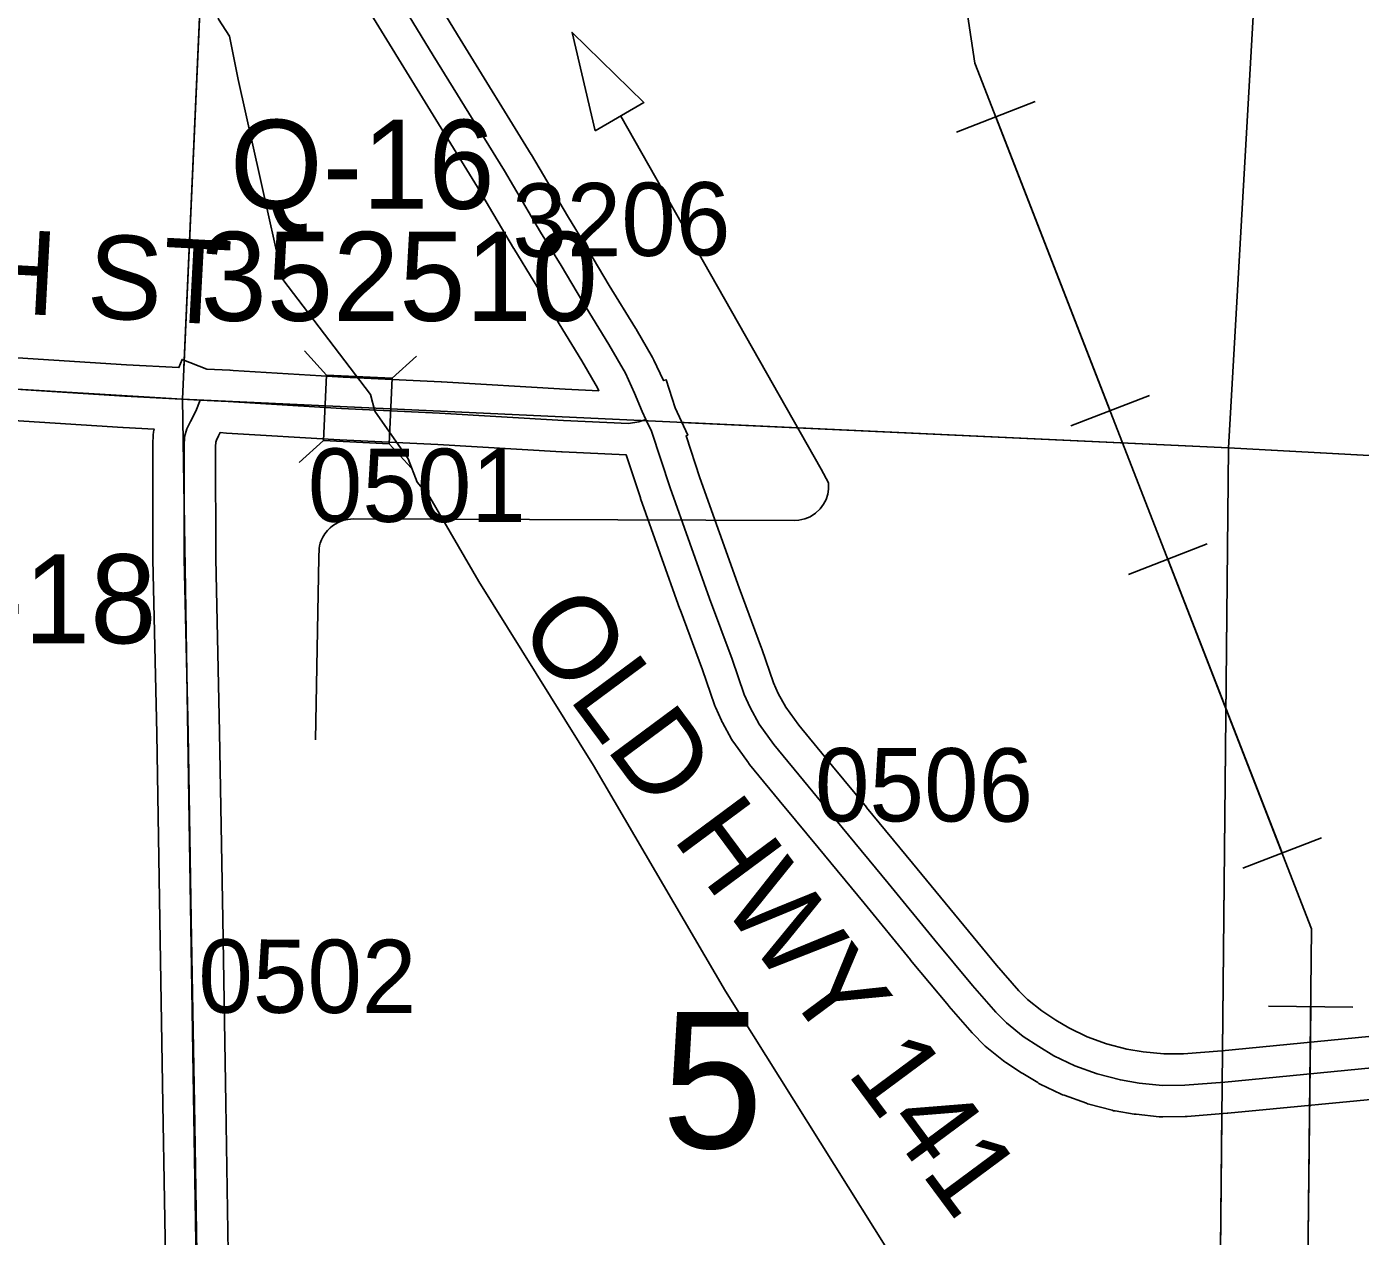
# Model space of a CAD drawing. Extents: x -157.2 to -99.3, y 12.2 to 46.2.
# Drawn here: x -139.945 to -138.672, y 28.173 to 29.328 of the extents above; entities that cross this region are included whole.
import ezdxf

# ---------------------------------------------------------------- set-up
doc = ezdxf.new("R2010")
doc.units = 0
for name, color, linetype in [('tdCoDirctArrow', 7, 'Continuous'), ('tdCoHydroRiver', 7, 'Continuous'), ('tdCoPipe', 7, 'Continuous'), ('tdCoSecRdNmbr', 7, 'Continuous'), ('tdCoSecRdTxt', 7, 'Continuous'), ('tdCoSecRteBand', 7, 'Continuous'), ('tdCoSecRteCL', 7, 'Continuous'), ('tdCoSectLine', 7, 'Continuous'), ('tdCoSectLinePart', 7, 'Continuous'), ('tdCoSectNmbr', 7, 'Continuous'), ('tdCoStrucSec', 7, 'Continuous'), ('tdCoStrucSecCoName', 7, 'Continuous'), ('tdCoStrucSecFHWANum', 7, 'Continuous'), ('tdCoSurfAsphalt', 7, 'Continuous'), ('tdCoSurfGravel', 7, 'Continuous'), ('tdCoTwpBndry', 7, 'Continuous'), ('tdCoTwpBndryShd', 7, 'Continuous')]:
    doc.layers.add(name, color=color, linetype=linetype)

msp = doc.modelspace()

# ---------------------------------------------------------------- linework, layer by layer
at = {"layer": 'tdCoDirctArrow'}
msp.add_lwpolyline([(-139.4023, 29.2282), (-139.4242, 29.3221), (-139.3557, 29.2552)], close=True, dxfattribs=at)
msp.add_lwpolyline([(-139.6693, 28.6465), (-139.666, 28.8206), (-139.6658, 28.8292), (-139.6653, 28.8319), (-139.6648, 28.8344), (-139.6636, 28.8375), (-139.6622, 28.8403), (-139.6602, 28.8434), (-139.6578, 28.8464), (-139.6553, 28.849), (-139.6531, 28.8509), (-139.6504, 28.8527), (-139.6476, 28.8542), (-139.6448, 28.8555), (-139.6422, 28.8563), (-139.6382, 28.8571), (-139.6332, 28.8576), (-139.2124, 28.856), (-139.2079, 28.8565), (-139.2021, 28.8576), (-139.1971, 28.8596), (-139.192, 28.8632), (-139.1875, 28.8672), (-139.1843, 28.8715), (-139.1818, 28.8761), (-139.1802, 28.8811), (-139.1795, 28.8861), (-139.1796, 28.8921), (-139.1864, 28.9051), (-139.3778, 29.242)], dxfattribs=at)
at = {"layer": 'tdCoHydroRiver'}
msp.add_lwpolyline([(-139.834, 29.7033), (-139.8556, 29.6693), (-139.879, 29.5784), (-139.8658, 29.5448), (-139.7953, 29.4273), (-139.7659, 29.3569), (-139.7619, 29.3347), (-139.7513, 29.3185), (-139.7431, 29.2772), (-139.7002, 29.0863), (-139.6168, 28.9763), (-139.6125, 28.9604), (-139.5808, 28.9151), (-139.572, 28.8928), (-139.5599, 28.8782), (-139.5134, 28.7977), (-139.4037, 28.6221), (-139.2778, 28.4065), (-139.0702, 28.0755)], dxfattribs=at)
at = {"layer": 'tdCoPipe'}
for p, q in [((-138.9822, 29.256), (-139.0573, 29.2268)), ((-138.8731, 28.9755), (-138.9481, 28.9463)), ((-138.818, 28.8338), (-138.8931, 28.8046)), ((-138.7089, 28.5532), (-138.7839, 28.524)), ((-138.6789, 28.3914), (-138.7595, 28.3923))]:
    msp.add_line(p, q, dxfattribs=at)
for points in [[(-136.934, 22.5495), (-137.7242, 24.8933), (-138.4968, 27.1666), (-138.4114, 27.2635), (-138.4614, 27.8735), (-138.7227, 28.0895), (-138.7183, 28.4663), (-139.0397, 29.2926), (-139.1184, 29.8198), (-140.0614, 32.629), (-140.3902, 33.7747), (-140.3873, 34.3489), (-140.6033, 34.3601), (-141.0238, 35.5765), (-141.1818, 36.0085), (-141.3937, 37.236), (-141.4233, 37.6118), (-141.6227, 37.7022), (-142.0941, 39.016), (-142.2605, 40.1621), (-142.7574, 40.5833), (-142.8772, 41.3829)], [(-138.9106, 28.9609), (-139.0197, 29.2414)], [(-138.7464, 28.5386), (-138.8555, 28.8192)], [(-138.7227, 28.0908), (-138.7192, 28.3918)]]:
    msp.add_lwpolyline(points, dxfattribs=at)
at = {"layer": 'tdCoSecRteBand'}
for points in [[(-139.5737, 29.3856), (-139.5311, 29.3158), (-139.4633, 29.2056), (-139.4632, 29.2054), (-139.463, 29.2052), (-139.4286, 29.1469), (-139.4092, 29.115), (-139.4091, 29.1149), (-139.4091, 29.1148), (-139.3887, 29.0806), (-139.3636, 29.0396), (-139.3634, 29.0393), (-139.3632, 29.0389), (-139.3475, 29.0116), (-139.3468, 29.0104), (-139.3463, 29.0093), (-139.3374, 28.9903), (-139.3371, 28.9898), (-139.3371, 28.9896), (-139.3346, 28.9904), (-139.3257, 28.9635), (-139.3139, 28.9377), (-139.3155, 28.937), (-139.3022, 28.8968), (-139.2648, 28.7918), (-139.2435, 28.734), (-139.2433, 28.7337), (-139.2432, 28.7334), (-139.2321, 28.7011), (-139.2275, 28.6909), (-139.2203, 28.6777), (-139.2079, 28.6605), (-139.1757, 28.6214), (-139.1432, 28.5822), (-139.1432, 28.5822), (-139.1431, 28.5821), (-139.0992, 28.5289), (-139.0992, 28.5288), (-139.0992, 28.5288), (-139.0549, 28.4746), (-139.0192, 28.4316), (-138.9978, 28.4071), (-138.9895, 28.3986), (-138.976, 28.3878), (-138.9626, 28.3791), (-138.95, 28.3715), (-138.9327, 28.3631), (-138.9142, 28.3564), (-138.8946, 28.3512), (-138.879, 28.3487), (-138.8594, 28.3467), (-138.8406, 28.3469), (-138.8039, 28.3498), (-138.6375, 28.3658)], [(-139.9537, 29.0114), (-139.8495, 29.0047), (-139.7995, 29.0021), (-139.7965, 29.0098), (-139.7729, 29.0007), (-139.7508, 28.9996), (-139.7507, 28.9996), (-139.7507, 28.9996), (-139.7477, 28.9994), (-139.7477, 28.9994), (-139.6427, 28.9929), (-139.5492, 28.9885), (-139.5491, 28.9885), (-139.5489, 28.9884), (-139.4308, 28.9814), (-139.3988, 28.98), (-139.4001, 28.9827), (-139.415, 29.0086), (-139.44, 29.0495), (-139.4401, 29.0496), (-139.4401, 29.0498), (-139.4605, 29.0839), (-139.48, 29.1159), (-139.4801, 29.1161), (-139.4802, 29.1162), (-139.5145, 29.1744), (-139.5822, 29.2844), (-139.5822, 29.2845), (-139.5823, 29.2845), (-139.6249, 29.3543)], [(-139.8118, 28.1154), (-139.8148, 28.2986), (-139.8177, 28.4746), (-139.8177, 28.4746), (-139.8177, 28.4746), (-139.8207, 28.6526), (-139.8244, 28.8187), (-139.8244, 28.819), (-139.8244, 28.8193), (-139.8246, 28.9274), (-139.8246, 28.9283), (-139.8246, 28.9292), (-139.8241, 28.9376), (-139.8239, 28.9408), (-139.8232, 28.9433), (-139.8528, 28.9448), (-139.853, 28.9448), (-139.8532, 28.9448), (-139.9574, 28.9515)], [(-138.6318, 28.3061), (-138.7984, 28.29), (-138.7987, 28.29), (-138.799, 28.29), (-138.837, 28.287), (-138.838, 28.2869), (-138.8389, 28.2869), (-138.8604, 28.2867), (-138.8621, 28.2867), (-138.8637, 28.2868), (-138.8859, 28.2891), (-138.8869, 28.2891), (-138.8878, 28.2893), (-138.9058, 28.2923), (-138.9073, 28.2925), (-138.9087, 28.2929), (-138.9309, 28.2988), (-138.9321, 28.2991), (-138.9333, 28.2996), (-138.9545, 28.3072), (-138.956, 28.3077), (-138.9574, 28.3084), (-138.9773, 28.318), (-138.9786, 28.3186), (-138.9798, 28.3194), (-138.9941, 28.328), (-138.9946, 28.3283), (-138.9951, 28.3286), (-139.0101, 28.3385), (-139.0113, 28.3392), (-139.0124, 28.3401), (-139.0284, 28.3529), (-139.0299, 28.3541), (-139.0312, 28.3554), (-139.0413, 28.3658), (-139.0419, 28.3664), (-139.0424, 28.367), (-139.0646, 28.3924), (-139.0648, 28.3927), (-139.0651, 28.393), (-139.1011, 28.4364), (-139.1012, 28.4364), (-139.1012, 28.4365), (-139.1456, 28.4907), (-139.1894, 28.5439), (-139.2219, 28.5831), (-139.222, 28.5832), (-139.222, 28.5832), (-139.2548, 28.6232), (-139.2554, 28.6239), (-139.256, 28.6247), (-139.27, 28.6441), (-139.2711, 28.6456), (-139.272, 28.6473), (-139.2807, 28.6631), (-139.2812, 28.6641), (-139.2817, 28.6651), (-139.2874, 28.6777), (-139.2879, 28.679), (-139.2884, 28.6802), (-139.2998, 28.7135), (-139.3212, 28.7711), (-139.3213, 28.7713), (-139.3213, 28.7715), (-139.3588, 28.877), (-139.3589, 28.8773), (-139.359, 28.8776), (-139.3727, 28.9188), (-139.4337, 28.9215), (-139.4339, 28.9215), (-139.4342, 28.9215), (-139.5523, 28.9285), (-139.6458, 28.933), (-139.646, 28.933), (-139.6462, 28.933), (-139.7541, 28.9396), (-139.7602, 28.94), (-139.7618, 28.9369), (-139.7638, 28.9328), (-139.7644, 28.9308), (-139.7646, 28.9266), (-139.7644, 28.8198), (-139.7607, 28.6539), (-139.7607, 28.6538), (-139.7607, 28.6537), (-139.7577, 28.4756), (-139.7548, 28.2996), (-139.7548, 28.2996), (-139.7548, 28.2996), (-139.7518, 28.1163)]]:
    msp.add_lwpolyline(points, dxfattribs=at)
at = {"layer": 'tdCoSecRteCL'}
for points in [[(-139.3537, 28.9524), (-139.3572, 28.9601), (-139.3646, 28.9776), (-139.3734, 28.9966), (-139.3892, 29.024), (-139.4144, 29.0651), (-139.4348, 29.0994), (-139.4543, 29.1315), (-139.4889, 29.1899), (-139.5567, 29.3002), (-139.5993, 29.3699)], [(-141.7835, 29.0328), (-141.7275, 29.0325), (-141.5837, 29.0322), (-141.4675, 29.0322), (-141.3625, 29.0335), (-141.1741, 29.0325), (-141.0592, 29.0325), (-140.9654, 29.0322), (-140.8404, 29.032), (-140.7795, 29.0315), (-140.7129, 29.0276), (-140.5687, 29.0169), (-140.5058, 29.0135), (-140.3884, 29.0046), (-140.3223, 28.997), (-140.2853, 28.995), (-140.2646, 28.9955), (-140.2155, 28.9962), (-140.1699, 28.994), (-140.1206, 28.9913), (-140.0133, 28.9846), (-139.9556, 28.9814), (-139.8513, 28.9748), (-139.7793, 28.971)], [(-139.7915, 26.9754), (-139.789, 27.1141), (-139.7867, 27.29), (-139.7853, 27.4549), (-139.7835, 27.633), (-139.7818, 27.8022), (-139.7798, 27.9708), (-139.7818, 28.1158), (-139.7848, 28.2991), (-139.7877, 28.4751), (-139.7907, 28.6532), (-139.7944, 28.8194), (-139.7946, 28.9274), (-139.7941, 28.9358), (-139.7919, 28.9437), (-139.7885, 28.9506), (-139.7833, 28.9605), (-139.7793, 28.971)], [(-139.7793, 28.971), (-139.7524, 28.9696), (-139.6444, 28.9629), (-139.5507, 28.9585), (-139.4324, 28.9514), (-139.3705, 28.9487), (-139.3604, 28.9502), (-139.3537, 28.9524)], [(-138.6346, 28.3359), (-138.8013, 28.3199), (-138.8393, 28.3169), (-138.8607, 28.3167), (-138.8829, 28.3189), (-138.9009, 28.3219), (-138.9231, 28.3278), (-138.9443, 28.3354), (-138.9643, 28.345), (-138.9786, 28.3537), (-138.9937, 28.3635), (-139.0097, 28.3764), (-139.0198, 28.3867), (-139.042, 28.4121), (-139.078, 28.4555), (-139.1224, 28.5098), (-139.1663, 28.563), (-139.1988, 28.6023), (-139.2316, 28.6422), (-139.2457, 28.6617), (-139.2543, 28.6775), (-139.26, 28.69), (-139.2716, 28.7236), (-139.293, 28.7815), (-139.3305, 28.8871), (-139.3485, 28.9413), (-139.3537, 28.9524)]]:
    msp.add_lwpolyline(points, dxfattribs=at)
at = {"layer": 'tdCoSectLine'}
for points in [[(-139.7961, 28.9719), (-139.7503, 29.9964)], [(-138.7976, 28.9254), (-138.7411, 29.9168)], [(-140.7866, 29.0316), (-139.7961, 28.9719)], [(-139.7961, 28.9719), (-138.7976, 28.9254)], [(-139.7803, 27.9656), (-139.7961, 28.9719)], [(-138.8076, 27.9332), (-138.7976, 28.9254)], [(-138.7976, 28.9254), (-137.7864, 28.8705)]]:
    msp.add_lwpolyline(points, dxfattribs=at)
at = {"layer": 'tdCoSectLinePart'}
for points in [[(-138.7976, 28.9254), (-138.7411, 29.9168)], [(-139.7948, 29.0017), (-139.769, 29.5789)], [(-139.3201, 28.9497), (-138.7976, 28.9254)], [(-138.8034, 28.3498), (-138.7976, 28.9254)], [(-138.7976, 28.9254), (-138.0562, 28.8851)], [(-138.8076, 27.9332), (-138.804, 28.2902)]]:
    msp.add_lwpolyline(points, dxfattribs=at)
at = {"layer": 'tdCoStrucSec'}
for p, q in [((-139.6586, 28.9949), (-139.6796, 29.0181)), ((-139.596, 28.992), (-139.5729, 29.013)), ((-139.6615, 28.9324), (-139.6847, 28.9113)), ((-139.599, 28.9294), (-139.5779, 28.9063))]:
    msp.add_line(p, q, dxfattribs=at)
msp.add_lwpolyline([(-139.6586, 28.9949), (-139.596, 28.992), (-139.599, 28.9294), (-139.6615, 28.9324)], close=True, dxfattribs=at)
at = {"layer": 'tdCoSurfAsphalt'}
for points in [[(-139.3537, 28.9524), (-139.3572, 28.9601), (-139.3646, 28.9776), (-139.3734, 28.9966), (-139.3892, 29.024), (-139.4144, 29.0651), (-139.4348, 29.0994), (-139.4543, 29.1315), (-139.4889, 29.1899), (-139.5567, 29.3002), (-139.5993, 29.3699), (-139.6228, 29.4082), (-139.6353, 29.4279), (-139.657, 29.4629), (-139.6778, 29.4966)], [(-138.6346, 28.3359), (-138.8013, 28.3199), (-138.8393, 28.3169), (-138.8607, 28.3167), (-138.8829, 28.3189), (-138.9009, 28.3219), (-138.9231, 28.3278), (-138.9443, 28.3354), (-138.9643, 28.345), (-138.9786, 28.3537), (-138.9937, 28.3635), (-139.0097, 28.3764), (-139.0198, 28.3867), (-139.042, 28.4121), (-139.078, 28.4555), (-139.1224, 28.5098), (-139.1663, 28.563), (-139.1988, 28.6023), (-139.2316, 28.6422), (-139.2457, 28.6617), (-139.2543, 28.6775), (-139.26, 28.69), (-139.2716, 28.7236), (-139.293, 28.7815), (-139.3305, 28.8871), (-139.3485, 28.9413), (-139.3537, 28.9524)]]:
    msp.add_lwpolyline(points, dxfattribs=at)
at = {"layer": 'tdCoSurfGravel'}
for points in [[(-139.9556, 28.9814), (-139.8513, 28.9748), (-139.7793, 28.971)], [(-139.803, 26.6128), (-139.7971, 26.7869), (-139.7917, 26.9627), (-139.7915, 26.9754), (-139.789, 27.1141), (-139.7867, 27.29), (-139.7853, 27.4549), (-139.7835, 27.633), (-139.7818, 27.8022), (-139.7798, 27.9708), (-139.7818, 28.1158), (-139.7848, 28.2991), (-139.7877, 28.4751), (-139.7907, 28.6532), (-139.7944, 28.8194), (-139.7946, 28.9274), (-139.7941, 28.9358), (-139.7919, 28.9437), (-139.7885, 28.9506), (-139.7833, 28.9605), (-139.7793, 28.971)], [(-139.7793, 28.971), (-139.7524, 28.9696), (-139.6444, 28.9629), (-139.5507, 28.9585), (-139.4324, 28.9514), (-139.3705, 28.9487), (-139.3604, 28.9502), (-139.3537, 28.9524)]]:
    msp.add_lwpolyline(points, dxfattribs=at)
at = {"layer": 'tdCoTwpBndry'}
msp.add_lwpolyline([(-138.0564, 28.8851), (-138.7976, 28.9254), (-139.3197, 28.9497)], dxfattribs=at)
at = {"layer": 'tdCoTwpBndryShd'}
msp.add_lwpolyline([(-148.6552, 29.1359), (-147.7617, 29.1108), (-146.7666, 29.0737), (-145.7949, 29.0582), (-144.7725, 29.0447), (-143.7799, 29.0389), (-142.7824, 29.0379), (-141.7839, 29.0328), (-140.7866, 29.0316), (-139.7961, 28.9719), (-138.7976, 28.9254), (-137.7864, 28.8705), (-136.7821, 28.8176), (-135.7696, 28.7544), (-134.7778, 28.6994), (-133.8175, 28.674)], dxfattribs=at)

# ---------------------------------------------------------------- texts
at = {"layer": 'tdCoSecRdNmbr'}
for s, rotation, p in [('3206', 0.4481, (-139.4811, 29.1077)), ('0501', 359.8938, (-139.6766, 28.8549)), ('0506', 359.8938, (-139.1925, 28.5689)), ('0502', 359.8938, (-139.7811, 28.3861))]:
    msp.add_text(s, height=0.07, rotation=rotation, dxfattribs=at).set_placement(p)
at = {"layer": 'tdCoSecRdTxt'}
for s, rotation, p in [('220TH ST', 356.9221, (-140.2388, 29.0689)), ('OLD HWY 141', 306.5813, (-139.4781, 28.7535))]:
    msp.add_text(s, height=0.08, rotation=rotation, dxfattribs=at).set_placement(p)
at = {"layer": 'tdCoSectNmbr'}
msp.add_text('5', height=0.13, rotation=359.8941, dxfattribs=at).set_placement((-139.3387, 28.2569))
at = {"layer": 'tdCoStrucSecCoName'}
for s, p in [('Q-16', (-139.7508, 29.1537)), ('GRANGE Q-18', (-140.5979, 28.7388))]:
    msp.add_text(s, height=0.085, dxfattribs=at).set_placement(p)
at = {"layer": 'tdCoStrucSecFHWANum'}
msp.add_text('352510', height=0.085, dxfattribs=at).set_placement((-139.7789, 29.0467))

doc.saveas('drawing.dxf')
